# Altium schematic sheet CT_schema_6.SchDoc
size 445 x 328 mm
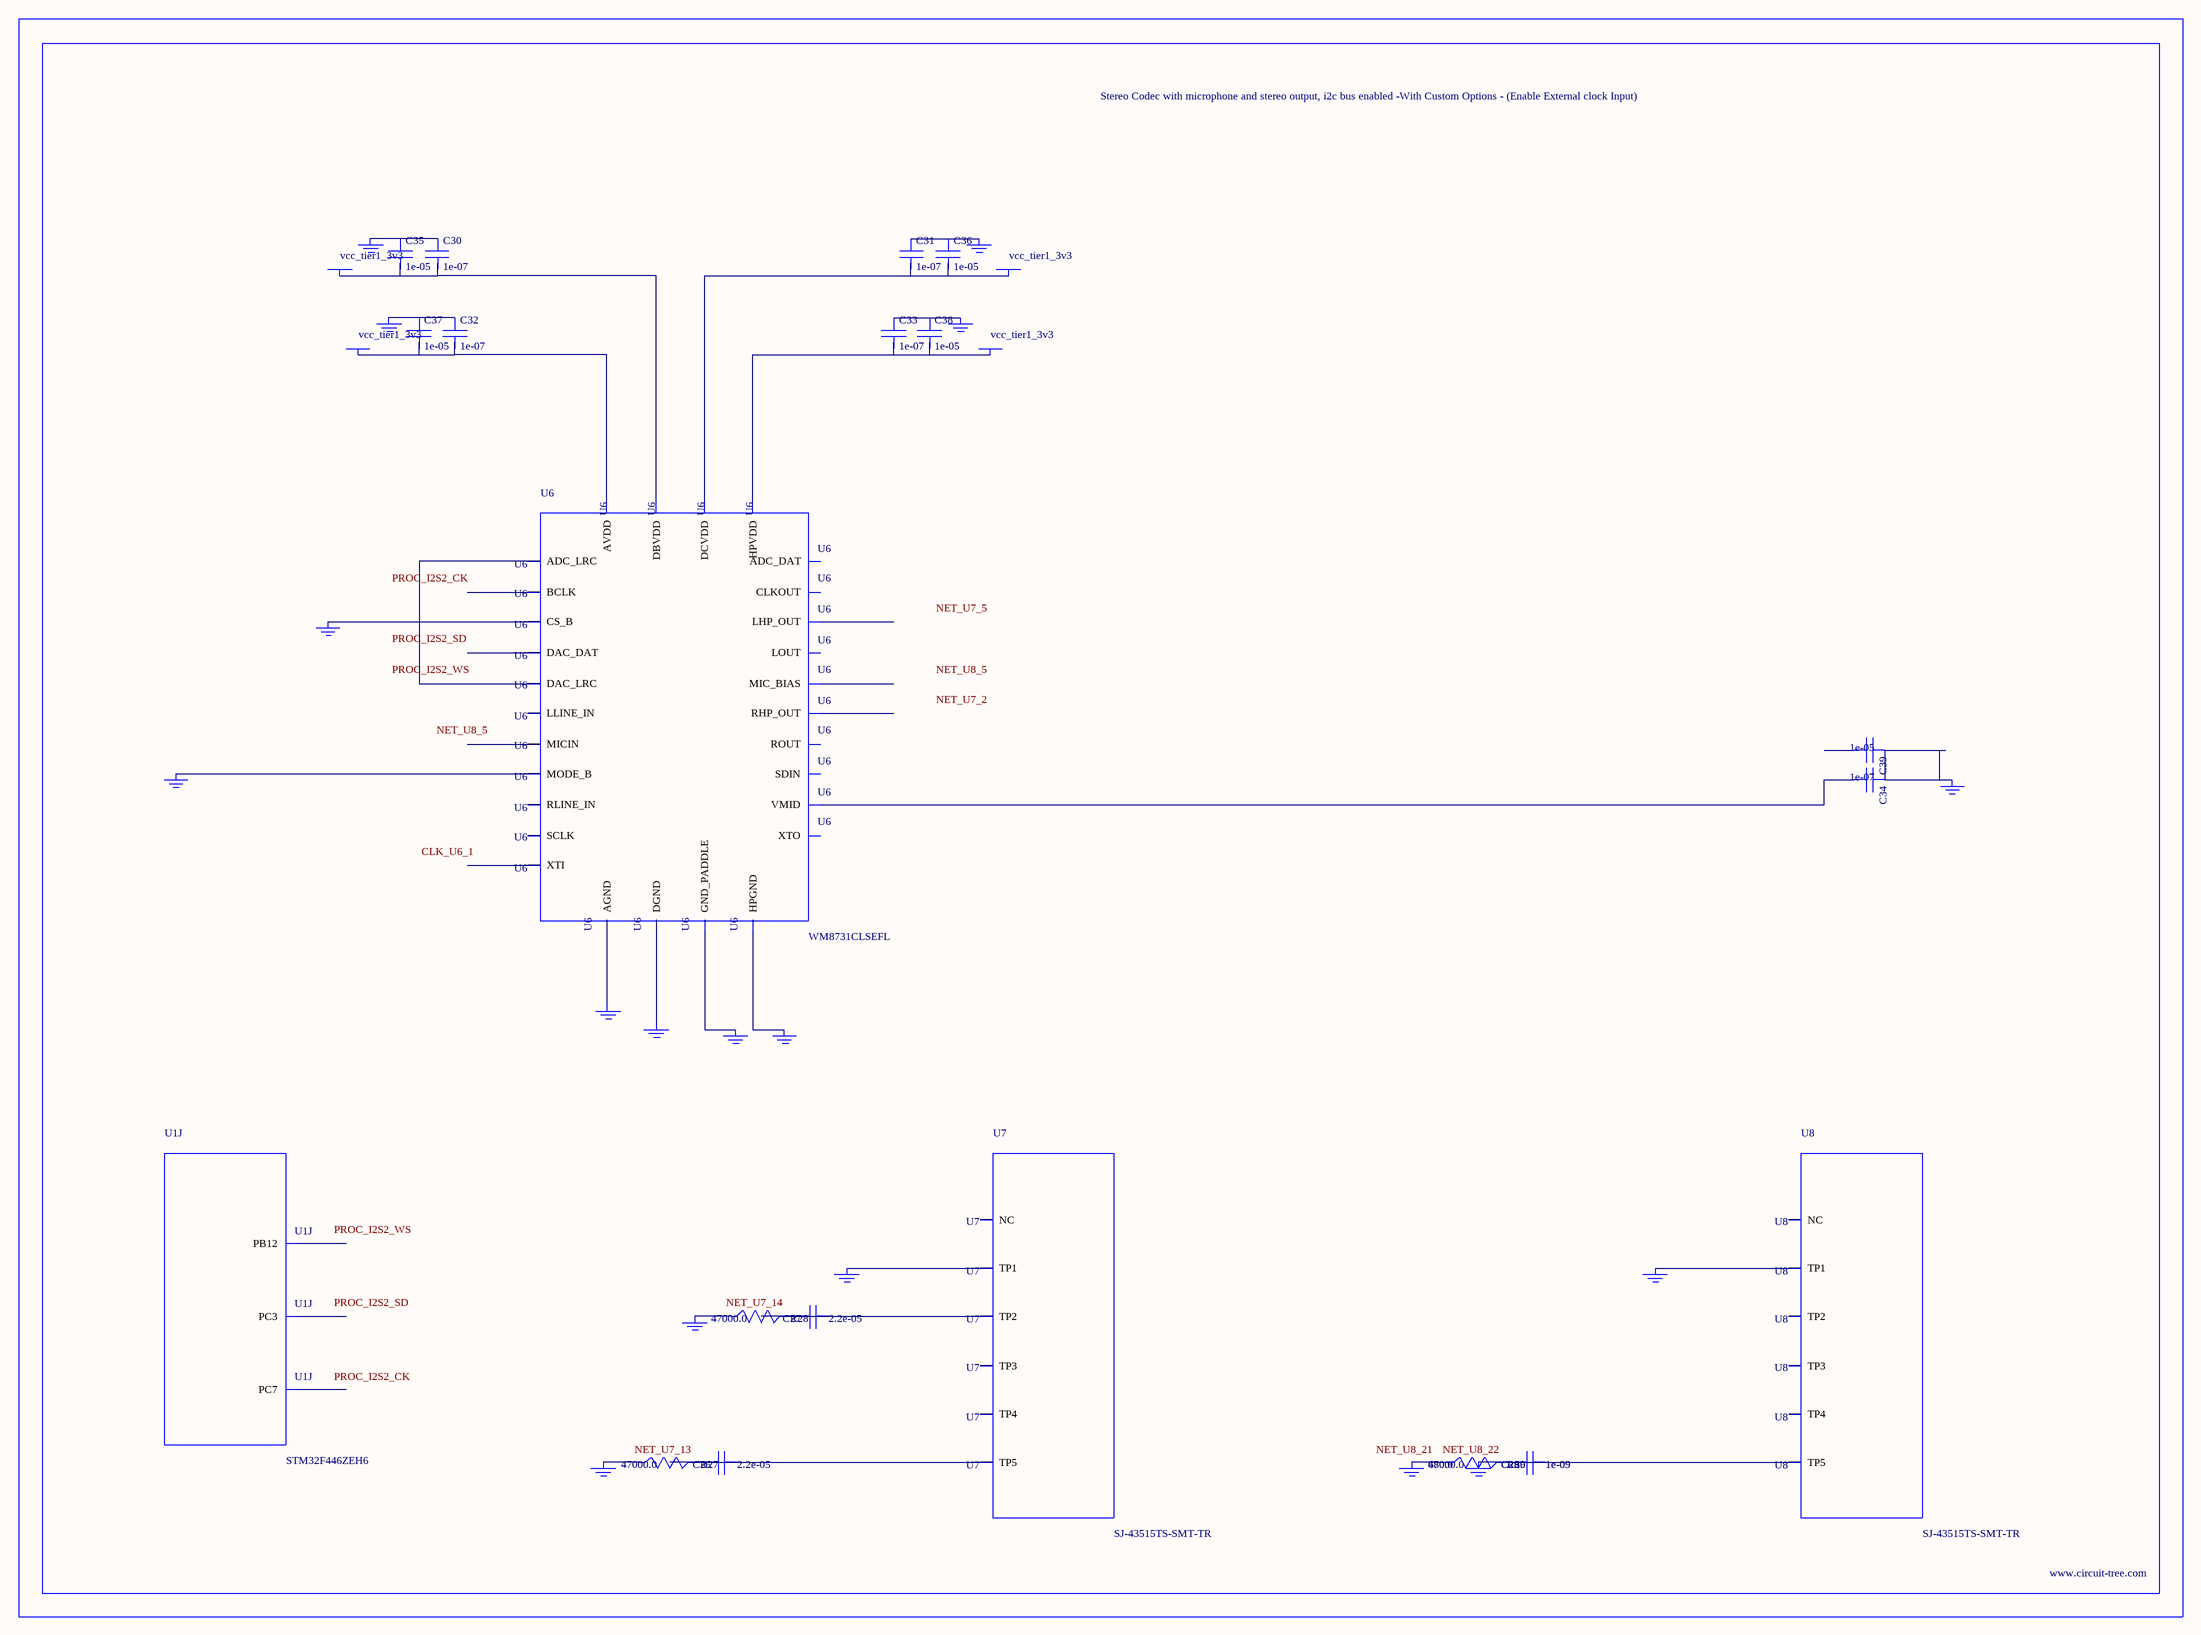
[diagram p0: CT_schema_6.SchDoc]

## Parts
BORDER5  (no value)
C26  2.2e-05  [C1210]
C27  2.2e-05  [C1210]
C28  1e-09  [C0402]
C29  1e-09  [C0402]
C30  1e-07  [C0402]
C31  1e-07  [C0402]
C32  1e-07  [C0402]
C33  1e-07  [C0402]
C34  1e-07  [C0402]
C35  1e-05  [C0805]
C36  1e-05  [C0805]
C37  1e-05  [C0805]
C38  1e-05  [C0805]
C39  1e-05  [C0805]
GND_INSTANCE_5_0  (no value)
GND_INSTANCE_5_1  (no value)
GND_INSTANCE_5_2  (no value)
GND_INSTANCE_5_3  (no value)
GND_INSTANCE_5_4  (no value)
GND_INSTANCE_5_5  (no value)
GND_INSTANCE_5_6  (no value)
GND_INSTANCE_5_7  (no value)
GND_INSTANCE_5_8  (no value)
GND_INSTANCE_5_9  (no value)
GND_INSTANCE_5_10  (no value)
GND_INSTANCE_5_11  (no value)
GND_INSTANCE_5_12  (no value)
GND_INSTANCE_5_13  (no value)
GND_INSTANCE_5_14  (no value)
GND_INSTANCE_5_15  (no value)
GND_INSTANCE_5_16  (no value)
POWER_INSTANCE_5_0  vcc_tier1_3v3
POWER_INSTANCE_5_1  vcc_tier1_3v3
POWER_INSTANCE_5_2  vcc_tier1_3v3
POWER_INSTANCE_5_3  vcc_tier1_3v3
R27  47000.0  [R0603]
R28  47000.0  [R0603]
R29  47000.0  [R0603]
R30  680.0  [R0603]
U1  STM32F446ZEH6  [UFBGA144]  (part J of 10)
U6  WM8731CLSEFL  [QFN-28]
U7  SJ-43515TS-SMT-TR  [SJ-43515TS-SMT-TR]
U8  SJ-43515TS-SMT-TR  [SJ-43515TS-SMT-TR]

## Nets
NetC26_1: C26.1 C26.2 R27.2 U7.5(TP5)
NetC27_1: C27.1 C27.2 R28.2 U7.2(TP2)
NetC28_1: C28.1 C28.2 C29.1 C29.2 GND_INSTANCE_5_16.0(GND) R29.2 R30.2 U8.5(TP5)
NetC30_1: C30.1 C35.1 GND_INSTANCE_5_1.0(GND)
NetC30_2: C30.2 C35.2 POWER_INSTANCE_5_1.0(PWR) U6.5(DBVDD)
NetC31_1: C31.1 C36.1 GND_INSTANCE_5_0.0(GND)
NetC31_2: C31.2 C36.2 POWER_INSTANCE_5_0.0(PWR) U6.3(DCVDD)
NetC32_1: C32.1 C37.1 GND_INSTANCE_5_4.0(GND)
NetC32_2: C32.2 C37.2 POWER_INSTANCE_5_3.0(PWR) U6.18(AVDD)
NetC33_1: C33.1 C38.1 GND_INSTANCE_5_2.0(GND)
NetC33_2: C33.2 C38.2 POWER_INSTANCE_5_2.0(PWR) U6.12(HPVDD)
NetC34_1: C34.1 C39.1 GND_INSTANCE_5_5.0(GND)
NetC34_2: C34.2 U6.20(VMID)
NetGND_INSTANCE_5_3_0: GND_INSTANCE_5_3.0(GND) U6.15(HPGND)
NetGND_INSTANCE_5_6_0: GND_INSTANCE_5_6.0(GND) U6.25(MODE_B)
NetGND_INSTANCE_5_7_0: GND_INSTANCE_5_7.0(GND) U6.26(CS_B)
NetGND_INSTANCE_5_8_0: GND_INSTANCE_5_8.0(GND) U6.29(GND_PADDLE)
NetGND_INSTANCE_5_9_0: GND_INSTANCE_5_9.0(GND) U6.4(DGND)
NetGND_INSTANCE_5_10_0: GND_INSTANCE_5_10.0(GND) U6.19(AGND)
NetGND_INSTANCE_5_11_0: GND_INSTANCE_5_11.0(GND) U7.1(TP1)
NetGND_INSTANCE_5_12_0: GND_INSTANCE_5_12.0(GND) R28.1
NetGND_INSTANCE_5_13_0: GND_INSTANCE_5_13.0(GND) R27.1
NetGND_INSTANCE_5_14_0: GND_INSTANCE_5_14.0(GND) U8.1(TP1)
NetGND_INSTANCE_5_15_0: GND_INSTANCE_5_15.0(GND) R29.1 R30.1
NetU6_9: U6.9(DAC_LRC) U6.11(ADC_LRC)

Not connected (* = marked no-connect by the designer): C39 2; U1 F12(PC7) H4(PC3) M11(PB12); U6 1(XTI) 2(XTO) 6(CLKOUT) 7(BCLK) 8(DAC_DAT) 10(ADC_DAT) 13(LHP_OUT) 14(RHP_OUT) 16(LOUT) 17(ROUT) 21(MIC_BIAS) 22(MICIN) 23(RLINE_IN) 24(LLINE_IN) 27(SDIN) 28(SCLK); U7 3(TP3) 4(TP4) 6(NC); U8 2(TP2) 3(TP3) 4(TP4) 6(NC)

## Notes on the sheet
- Labels drawn without touching a wire or pin: CLK_U6_1, NET_U7_2, NET_U7_5, NET_U7_13, NET_U7_14, NET_U8_5, NET_U8_21, NET_U8_22, PROC_I2S2_CK, PROC_I2S2_SD, PROC_I2S2_WS

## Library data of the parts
BORDER5 = BORDER_PAGE5
C26 C27 = C1210C224K5RACTU
C28 C29 = C0402C102K3RAC
C30-C34 = C0402C104K3RACTU
C35-C39 = C0805C106K8RACTU
GND_INSTANCE_5_0-GND_INSTANCE_5_16 = GND
POWER_INSTANCE_5_0-POWER_INSTANCE_5_3 = PWR
R27-R29 = RC0603JR-0747KL
R30 = RC0603JR-07680RL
